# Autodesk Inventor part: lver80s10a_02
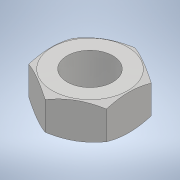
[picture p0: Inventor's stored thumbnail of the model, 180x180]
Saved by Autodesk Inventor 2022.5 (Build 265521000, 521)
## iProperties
Part Number: lver80s10a_02
Material: 一般
Document SubType Name: Modeling
Designer: ImaoCorp
Density: 1 g/cm^3
Appearance: 既定
Author: ImaoCorp
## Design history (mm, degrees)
feature "lver80s10a_02"
node "ソリッド1"
